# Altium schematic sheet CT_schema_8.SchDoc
size 251 x 159 mm
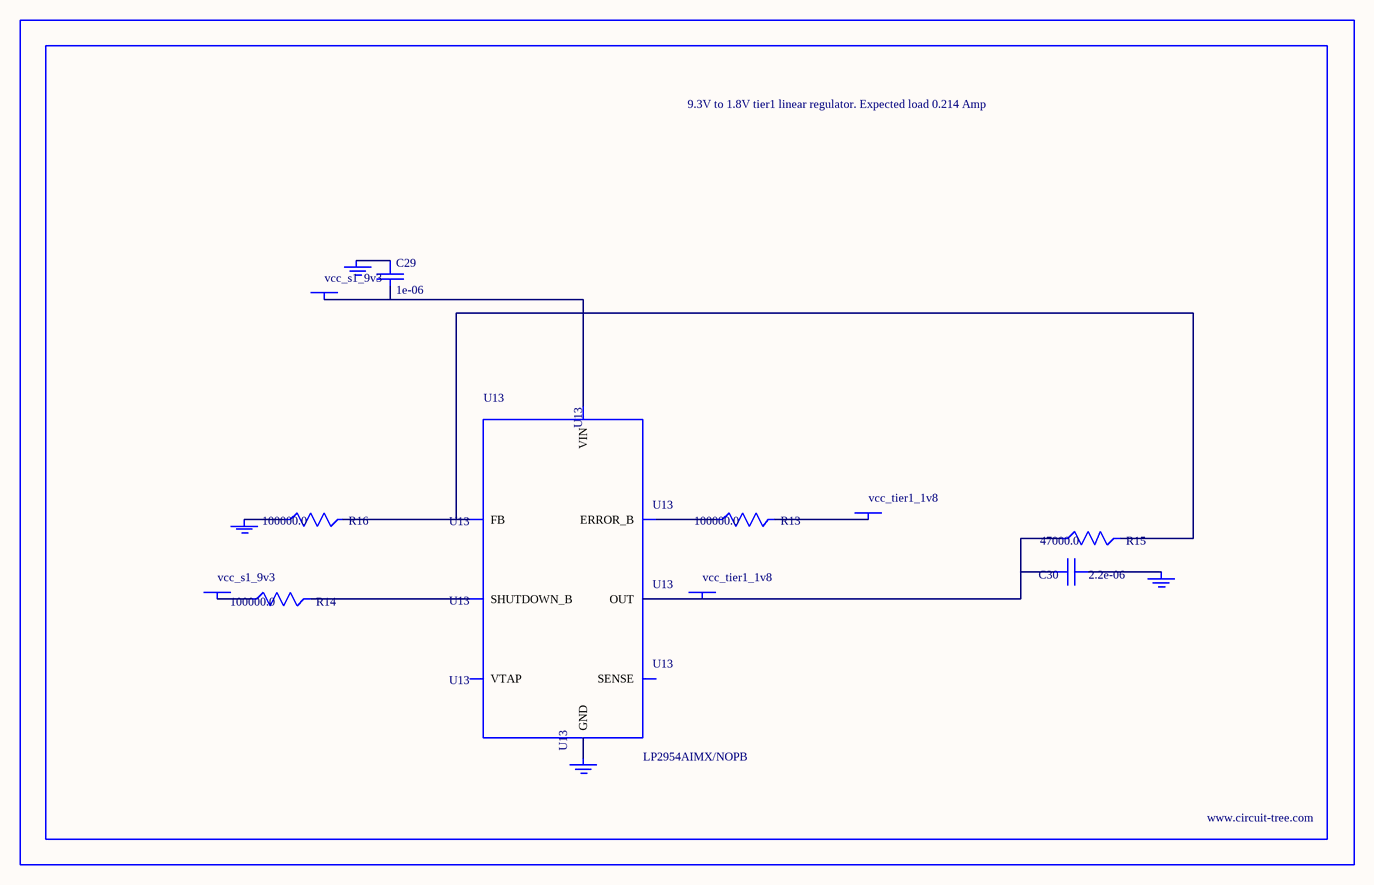
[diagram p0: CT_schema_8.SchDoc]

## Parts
BORDER7  (no value)
C29  1e-06  [EXV-9B]
C30  2.2e-06  [EXV-9B]
GND_INSTANCE_7_0  (no value)
GND_INSTANCE_7_1  (no value)
GND_INSTANCE_7_2  (no value)
GND_INSTANCE_7_3  (no value)
POWER_INSTANCE_7_0  vcc_s1_9v3
POWER_INSTANCE_7_1  vcc_tier1_1v8
POWER_INSTANCE_7_2  vcc_s1_9v3
POWER_INSTANCE_7_3  vcc_tier1_1v8
R13  100000.0  [R0603]
R14  100000.0  [R0603]
R15  47000.0  [R0603]
R16  100000.0  [R0603]
U13  LP2954AIMX/NOPB  [LP2954]

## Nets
NetC29_1: C29.1 GND_INSTANCE_7_2.0(GND)
NetC29_2: C29.2 POWER_INSTANCE_7_2.0(PWR) U13.8(VIN)
NetC30_1: C30.1 GND_INSTANCE_7_0.0(GND)
NetC30_2: C30.2 POWER_INSTANCE_7_3.0(PWR) R15.1 U13.1(OUT)
NetGND_INSTANCE_7_1_0: GND_INSTANCE_7_1.0(GND) R16.1
NetGND_INSTANCE_7_3_0: GND_INSTANCE_7_3.0(GND) U13.4(GND)
NetPOWER_INSTANCE_7_0_0: POWER_INSTANCE_7_0.0(PWR) R14.1
NetPOWER_INSTANCE_7_1_0: POWER_INSTANCE_7_1.0(PWR) R13.2
NetR13_1: R13.1 U13.5(ERROR_B)
NetR14_2: R14.2 U13.3(SHUTDOWN_B)
NetR15_2: R15.2 R16.2 U13.7(FB)

Not connected (* = marked no-connect by the designer): U13 2(SENSE) 6(VTAP)

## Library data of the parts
BORDER7 = BORDER_PAGE7
C29 = EDK105M050A9BAA
C30 = EDK225M050A9BAA
GND_INSTANCE_7_0-GND_INSTANCE_7_3 = GND
POWER_INSTANCE_7_0-POWER_INSTANCE_7_3 = PWR
R13 R14 R16 = RC0603JR-07100KL
R15 = RC0603JR-0747KL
